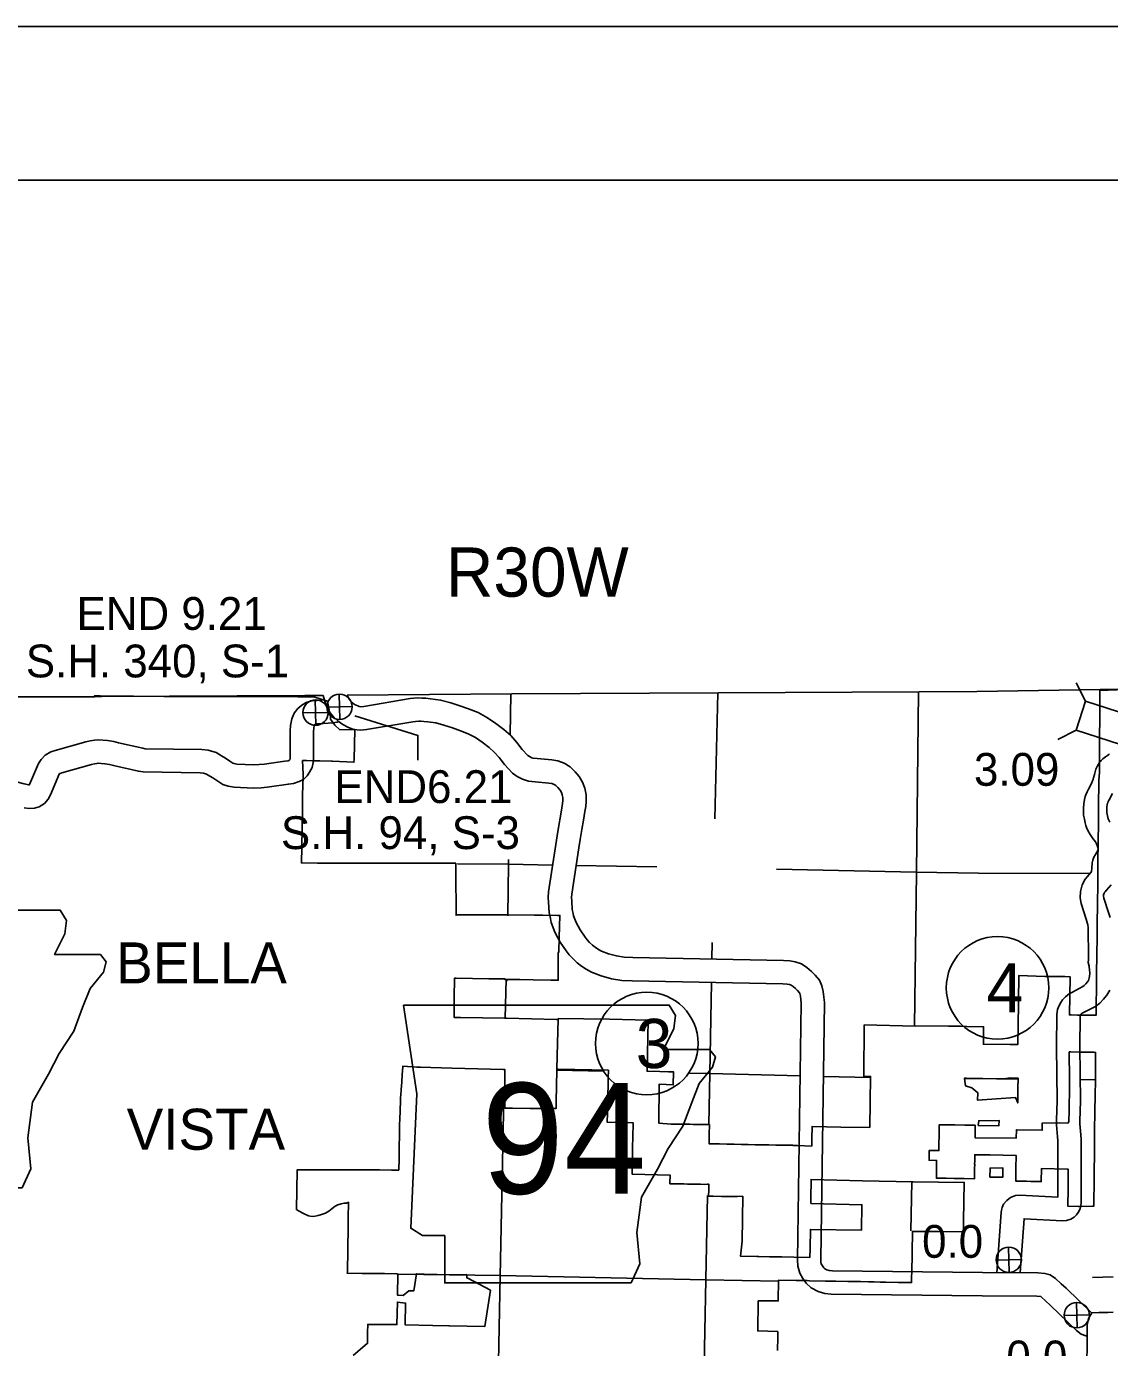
# Model space of a CAD drawing. Extents: x 77230 to 630905, y 790554 to 1662844.
# Drawn here: x 232709 to 260599, y 1621421 to 1655440 of the extents above; entities that cross this region are included whole.
import ezdxf

# ---------------------------------------------------------------- set-up
doc = ezdxf.new("R2010")
doc.units = 0
for name, color, linetype in [('Level 12', 7, 'Continuous'), ('Level 14', 7, 'Continuous'), ('Level 16', 7, 'Continuous'), ('Level 19', 7, 'Continuous'), ('Level 22', 7, 'Continuous'), ('Level 24', 7, 'Continuous'), ('Level 27', 7, 'Continuous'), ('Level 28', 7, 'Continuous'), ('Level 31', 7, 'Continuous'), ('Level 32', 7, 'Continuous'), ('Level 33', 7, 'Continuous'), ('Level 34', 7, 'Continuous')]:
    doc.layers.add(name, color=color, linetype=linetype)

msp = doc.modelspace()

# ---------------------------------------------------------------- linework, layer by layer
at = {"layer": 'Level 12'}
for points in [[(232156, 1638165), (233990, 1638176), (234030, 1638177), (234467, 1638179), (234460, 1638204), (234607, 1638202), (235470, 1638195), (236248, 1638188), (237126, 1638186), (238276, 1638185), (238909, 1638184), (238943, 1638183), (238967, 1638183), (238981, 1638183), (239696, 1638175), (239859, 1638174), (240133, 1638172), (240460, 1638068), (240502, 1637834), (240487, 1637833), (240529, 1637759), (240535, 1637603), (240653, 1637446), (240780, 1637327), (241114, 1637334), (241164, 1637335), (241144, 1636564), (241142, 1636494), (240590, 1636519), (240566, 1636520), (240265, 1636527), (240104, 1636531), (239917, 1636536), (239856, 1636538), (239822, 1636536), (239834, 1636177), (239832, 1636087), (239832, 1636074), (239831, 1636022), (239831, 1636014), (239830, 1636003)], [(260281, 1632286), (260288, 1632882), (260294, 1633326), (260296, 1633542), (260297, 1633575), (260297, 1633612), (260298, 1633714), (260301, 1633909), (260307, 1634453), (260313, 1634927), (260318, 1635179), (260317, 1635184), (260316, 1635188), (260317, 1635269), (260317, 1635294), (260318, 1635312), (260326, 1636044), (260330, 1636118), (260337, 1636245), (260340, 1636766), (260341, 1636820), (260341, 1636834), (260343, 1637228), (260347, 1637543), (260347, 1637562), (260347, 1637581), (260352, 1638340), (260999, 1638368)], [(239830, 1636003), (239821, 1635537), (239820, 1635503), (239821, 1635497), (239821, 1635490), (239820, 1635481), (239819, 1635475), (239816, 1635279), (239798, 1634326), (239797, 1634269), (239791, 1633937), (239790, 1633899), (239801, 1633899), (240203, 1633898), (240628, 1633897), (240964, 1633896), (241291, 1633896), (241914, 1633895), (241922, 1633895), (242202, 1633895), (242466, 1633895), (243765, 1633893), (243765, 1633874), (243766, 1633784), (243766, 1633607), (243773, 1632632), (243773, 1632554), (243785, 1632563), (245097, 1632564), (245113, 1632563), (245794, 1632556), (245939, 1632555), (246004, 1632554), (246385, 1632550), (246410, 1632549), (246444, 1632549), (246426, 1631983), (246415, 1631622), (246403, 1631574), (246403, 1631498), (246402, 1631213), (246402, 1631204), (246402, 1630878), (246215, 1630884), (245759, 1630894), (245416, 1630895), (245398, 1630896), (245372, 1630895), (245338, 1630895), (245034, 1630896), (245034, 1630915), (244850, 1630916), (244737, 1630916), (244615, 1630917), (243774, 1630936), (243762, 1630936), (243744, 1630937), (243732, 1630937), (243729, 1630898), (243731, 1630891), (243731, 1630882), (243727, 1630474), (243725, 1630277), (243722, 1629985), (243722, 1629974), (243721, 1629924), (243823, 1629922), (243889, 1629921), (245020, 1629905), (245029, 1629905), (245030, 1629905), (245061, 1629904), (245070, 1629904), (246362, 1629868), (246403, 1629867), (246387, 1629261), (246369, 1628593), (246368, 1628561), (246350, 1627755), (246349, 1627711), (246346, 1627576), (246333, 1627575), (246306, 1627574), (245676, 1627576), (245223, 1627584), (245024, 1627588), (245024, 1627819), (245025, 1628585), (244982, 1628585), (244982, 1628579), (244330, 1628600), (243661, 1628617), (242856, 1628639), (242766, 1628641), (242401, 1628663), (242399, 1628644), (242394, 1628562), (242385, 1628435), (242384, 1628426), (242374, 1628279)], [(249641, 1625634), (249540, 1625636), (249279, 1625640), (249279, 1625667), (249283, 1625861), (248957, 1625870), (248307, 1625882), (248319, 1626546), (248325, 1626874), (248330, 1627164), (248331, 1627212), (247667, 1627225), (247676, 1627680), (247678, 1627752), (247682, 1627954), (247686, 1628156), (247690, 1628358), (247694, 1628561), (246405, 1628589), (246369, 1628593), (246387, 1629261), (246403, 1629867), (246404, 1629894), (247722, 1629876), (248384, 1629864), (248715, 1629854), (248689, 1628535), (249020, 1628527), (249239, 1628521), (249372, 1628518), (249364, 1628186), (249003, 1628204), (248995, 1627197), (249310, 1627177), (249606, 1627173), (249698, 1627171), (249789, 1627170), (249880, 1627168), (249971, 1627166), (250072, 1627164), (250297, 1627163), (250290, 1626905), (250289, 1626807), (250289, 1626719), (250289, 1626672), (250293, 1626671), (250377, 1626669), (250467, 1626666), (250557, 1626663), (250747, 1626659), (250935, 1626655), (251115, 1626652), (251294, 1626648), (251474, 1626644), (251646, 1626640), (251825, 1626638), (252005, 1626635), (252113, 1626634), (252225, 1626632), (252261, 1626632), (252337, 1626630), (252434, 1626629), (252450, 1626628), (252564, 1626626), (252932, 1626611), (252934, 1626724), (252936, 1626840), (252940, 1627070), (252941, 1627114), (253683, 1627093), (254425, 1627091), (254445, 1628402), (254271, 1628406), (254281, 1629729), (255592, 1629697), (255592, 1629709), (256451, 1629697), (256757, 1629693), (256921, 1629690), (257342, 1629683), (257356, 1629683), (257350, 1629233), (258035, 1629224), (258233, 1629222), (258243, 1629668), (258262, 1630999), (258936, 1630978), (259238, 1630974), (259447, 1630972), (259582, 1630970), (259564, 1629986), (259609, 1629986), (259772, 1629984), (259995, 1629981), (260170, 1629979), (260253, 1629978), (260265, 1630961), (260273, 1631624), (260277, 1631901), (260281, 1632286)], [(242374, 1628279), (242373, 1628265), (242366, 1628154), (242365, 1628144), (242361, 1628084), (242360, 1628069), (242359, 1628059), (242358, 1628042), (242356, 1628008), (242354, 1627974), (242351, 1627936), (242345, 1627852), (242345, 1627843), (242343, 1627781), (242342, 1627762), (242321, 1627296), (242318, 1627174), (242316, 1627032), (242305, 1626448), (242305, 1626403), (242303, 1626338), (242303, 1626323), (242303, 1626290), (242297, 1625991), (242205, 1625992), (242112, 1625993), (241803, 1625994), (241701, 1625994), (241627, 1625995), (241589, 1625995), (241568, 1625995), (241056, 1625999), (241006, 1625999), (239680, 1625997), (239680, 1625993), (239659, 1624973), (239716, 1624946), (239863, 1624867), (239975, 1624809), (240070, 1624797), (240142, 1624807), (240222, 1624821), (240308, 1624846), (240406, 1624883), (240495, 1624935), (240581, 1625003), (240655, 1625062), (240730, 1625098), (240813, 1625124), (240888, 1625141), (240953, 1625143), (241000, 1625161), (240997, 1624755), (240997, 1624736), (240997, 1624674), (240995, 1624533), (240976, 1623375), (240971, 1623336), (241350, 1623332), (241926, 1623326), (242249, 1623321), (242275, 1623315), (242264, 1622770), (242281, 1622769), (242286, 1622769), (242414, 1622762), (242560, 1622878), (242684, 1622881), (242749, 1623320), (242947, 1623314), (243616, 1623294), (244046, 1623299), (244045, 1623221), (244075, 1623206), (244661, 1622898), (244517, 1621965), (243600, 1621978), (243585, 1621979), (243174, 1621991), (243167, 1621990), (242471, 1622007), (242461, 1622007), (242473, 1622566), (242261, 1622593), (242249, 1622011), (242228, 1622012), (242201, 1622012), (242132, 1622013), (242117, 1622013), (241969, 1622016), (241818, 1622015), (241668, 1622017), (241498, 1622018), (241496, 1621970), (241496, 1621958), (241491, 1621868), (241492, 1621718), (241493, 1621531), (241124, 1621221)], [(252050, 1621349), (252052, 1621449), (252054, 1621588), (252055, 1621697), (252056, 1621755), (252057, 1621833), (251539, 1621850), (251551, 1622622), (252069, 1622624), (252076, 1623153), (252076, 1623158), (252527, 1623148), (252816, 1623144), (252872, 1623143), (253282, 1623135), (253526, 1623131), (253548, 1623130), (253856, 1623125), (253977, 1623122), (254186, 1623119), (254388, 1623115), (254535, 1623112), (254689, 1623109), (254840, 1623106), (255160, 1623100), (255369, 1623096), (255500, 1623094), (255503, 1623279), (255504, 1623329), (255524, 1624414), (256184, 1624406), (256836, 1624398), (256840, 1624684), (256857, 1625674), (256197, 1625681), (255534, 1625688), (255534, 1625689), (254234, 1625716), (252915, 1625751), (252913, 1625528), (252911, 1625479), (252906, 1625290), (252908, 1625133), (254222, 1625100), (254210, 1624440), (252897, 1624465), (252888, 1623972), (252883, 1623742), (252472, 1623750), (252157, 1623756), (251843, 1623761), (251570, 1623768), (251517, 1623768), (251093, 1623777), (251137, 1624161), (251156, 1625318), (251022, 1625308), (250877, 1625311), (250842, 1625312), (250711, 1625315), (250606, 1625315), (250393, 1625318), (250275, 1625319), (250278, 1625481), (250281, 1625626), (250250, 1625627), (250167, 1625624), (250067, 1625625), (250016, 1625626), (249915, 1625628), (249824, 1625630), (249733, 1625632), (249641, 1625634)]]:
    msp.add_lwpolyline(points, dxfattribs=at)
for points in [[(259561, 1629037), (259570, 1628320), (259564, 1627926), (259562, 1627743), (259559, 1627560), (259559, 1627523), (259554, 1627231), (259528, 1627203), (259298, 1627205), (258865, 1627203), (258865, 1627019), (258199, 1627029), (258196, 1626814), (257138, 1626824), (257137, 1627038), (257138, 1627144), (257097, 1627147), (257010, 1627147), (256873, 1627148), (256617, 1627153), (256214, 1627159), (256213, 1627154), (256213, 1627131), (256212, 1627050), (256204, 1626498), (256203, 1626493), (255958, 1626498), (255953, 1626245), (256147, 1626241), (256139, 1625780), (256199, 1625784), (256395, 1625781), (256598, 1625773), (256851, 1625771), (257122, 1625767), (257124, 1625967), (257124, 1625969), (257125, 1626049), (257126, 1626127), (257125, 1626155), (257127, 1626208), (257128, 1626288), (257128, 1626388), (257328, 1626385), (257527, 1626382), (257859, 1626376), (258187, 1626370), (258191, 1626371), (258188, 1626039), (258187, 1626035), (258185, 1625801), (258183, 1625707), (258194, 1625706), (258207, 1625706), (258366, 1625704), (258463, 1625703), (258570, 1625701), (258670, 1625700), (258842, 1625697), (258848, 1626033), (259511, 1626015), (259537, 1626014), (259536, 1625930), (259533, 1625685), (259531, 1625509), (259530, 1625455), (259529, 1625354), (259527, 1625228), (259525, 1625059), (259801, 1625056), (259828, 1625056), (260158, 1625058), (260194, 1625058), (260197, 1625300), (260200, 1625556), (260201, 1625677), (260204, 1625922), (260211, 1626446), (260215, 1626991), (260221, 1627510), (260228, 1627916), (260233, 1628308), (260240, 1629023), (260190, 1629024), (260016, 1629027), (259860, 1629030), (259601, 1629036)], [(258241, 1628095), (258243, 1628361), (258057, 1628365), (257862, 1628343), (257688, 1628345), (257340, 1628350), (256919, 1628355), (256863, 1628356), (256873, 1628284), (256890, 1628158), (257051, 1628109), (257205, 1627983), (257205, 1627977), (257201, 1627790), (258178, 1627859), (258235, 1627719)], [(257220, 1627143), (257750, 1627134), (257760, 1627266), (257230, 1627261)], [(257523, 1626043), (257522, 1626043), (257522, 1626040), (257521, 1625963), (257520, 1625865), (257520, 1625809), (257850, 1625805), (257854, 1626047)]]:
    msp.add_lwpolyline(points, close=True, dxfattribs=at)
at = {"layer": 'Level 14'}
for points in [[(220456, 1638182), (224686, 1638186), (229993, 1638178), (234648, 1638189), (239874, 1638210), (240352, 1638214)], [(240968, 1638218), (245204, 1638251), (250522, 1638281), (255697, 1638310), (257182, 1638315)], [(257182, 1638315), (260885, 1638375)]]:
    msp.add_lwpolyline(points, dxfattribs=at)
at = {"layer": 'Level 16'}
for points in [[(245184, 1638244), (245169, 1637196)], [(250512, 1638279), (250433, 1635037)], [(255681, 1638306), (255627, 1633657), (255573, 1629697)], [(245121, 1633989), (245119, 1633866), (245102, 1632538)], [(243806, 1633877), (245123, 1633868), (246259, 1633847)], [(246866, 1633836), (248944, 1633798)], [(252027, 1633737), (255623, 1633661), (257222, 1633636)], [(257222, 1633636), (260098, 1633625)], [(250368, 1631855), (250360, 1631429)], [(245059, 1630907), (245039, 1629905)], [(245081, 1630896), (245081, 1630857)], [(250349, 1630821), (250307, 1628474), (250281, 1627165)], [(246368, 1628566), (247574, 1628538)], [(249782, 1628488), (250307, 1628476), (252632, 1628420)], [(253229, 1628405), (254445, 1628375)], [(256864, 1628347), (257278, 1628346)], [(258243, 1628336), (257278, 1628346)], [(260207, 1628317), (259839, 1628320)], [(244999, 1627881), (244910, 1623261), (244808, 1617974)], [(255508, 1625689), (255486, 1624424)], [(250245, 1625334), (250202, 1623165), (250100, 1617874)], [(242285, 1623309), (244914, 1623273), (250202, 1623167), (252076, 1623135)]]:
    msp.add_lwpolyline(points, dxfattribs=at)
at = {"layer": 'Level 19'}
for p, q in [((259979, 1638070), (259739, 1638541)), ((259735, 1637317), (259265, 1637077)), ((260691, 1623240), (260163, 1623223))]:
    msp.add_line(p, q, dxfattribs=at)
msp.add_lwpolyline([(262240, 1637339), (259979, 1638070), (259735, 1637317), (261996, 1636586)], close=True, dxfattribs=at)
at = {"layer": 'Level 22'}
for points in [[(234562, 1637067), (234800, 1637052), (234960, 1637024), (235083, 1636997), (235709, 1636852), (235769, 1636842), (237227, 1636824), (237392, 1636802), (237593, 1636741), (237732, 1636656), (237836, 1636599), (237945, 1636520), (238022, 1636472), (238056, 1636460), (238130, 1636447), (238558, 1636426), (238706, 1636433), (238836, 1636447), (239007, 1636471), (239242, 1636501), (239367, 1636525), (239448, 1636533), (239481, 1636546), (239484, 1636551), (239496, 1636572), (239499, 1636623), (239502, 1637302), (239508, 1637441), (239541, 1637615), (239605, 1637760), (239699, 1637879), (239801, 1637961), (239915, 1638034), (240080, 1638081), (240193, 1638085), (240380, 1638097)], [(240352, 1638214), (240406, 1638006), (240463, 1637878), (240528, 1637764), (240614, 1637659), (240732, 1637549), (240854, 1637466), (240989, 1637398), (241129, 1637339), (241311, 1637321), (241468, 1637334), (242662, 1637536), (242730, 1637542), (242809, 1637548), (242869, 1637547), (242945, 1637543), (243046, 1637533), (243252, 1637504), (243459, 1637448), (243678, 1637375), (243890, 1637304), (244083, 1637228), (244270, 1637127), (244442, 1637008), (244624, 1636869), (244755, 1636754), (244879, 1636614), (245021, 1636436), (245223, 1636215), (245346, 1636130), (245481, 1636056), (245637, 1636006), (245808, 1635990), (246162, 1635956), (246240, 1635943), (246295, 1635922), (246342, 1635896), (246391, 1635845), (246449, 1635776), (246483, 1635718), (246508, 1635651), (246523, 1635585), (246523, 1635512), (246514, 1635428), (246498, 1635321), (246459, 1635101), (246418, 1634863), (246371, 1634599), (246341, 1634377), (246151, 1633158), (246145, 1633009), (246151, 1632888), (246168, 1632625), (246200, 1632468), (246223, 1632369), (246317, 1632121), (246451, 1631864), (246606, 1631641), (246688, 1631530), (246787, 1631428), (246892, 1631328), (247006, 1631241), (247125, 1631161), (247259, 1631087), (247509, 1630989), (247773, 1630917), (248040, 1630874), (248306, 1630862), (252184, 1630786), (252295, 1630781), (252354, 1630769), (252401, 1630754), (252450, 1630721), (252513, 1630670), (252566, 1630612), (252612, 1630557), (252620, 1630540), (252637, 1630473), (252649, 1630387), (252655, 1630289), (252562, 1623684), (252570, 1623520), (252621, 1623341), (252701, 1623203), (252784, 1623082), (252913, 1622959), (253093, 1622864), (253267, 1622816), (253430, 1622799), (257321, 1622751)], [(240968, 1638218), (240999, 1638150), (241025, 1638105), (241052, 1638071), (241108, 1638019), (241159, 1637984), (241241, 1637943), (241277, 1637928), (241316, 1637924), (241394, 1637930), (242586, 1638132), (242682, 1638140), (242790, 1638148), (242890, 1638147), (242990, 1638141), (243117, 1638129), (243374, 1638093), (243633, 1638022), (243867, 1637944), (244095, 1637868), (244337, 1637773), (244584, 1637639), (244795, 1637494), (245004, 1637334), (245179, 1637180), (245339, 1637000), (245477, 1636825), (245620, 1636670), (245661, 1636641), (245719, 1636609), (245756, 1636597), (245864, 1636588), (246238, 1636551), (246396, 1636526), (246554, 1636466), (246712, 1636375), (246837, 1636248), (246942, 1636122), (247026, 1635977), (247084, 1635825), (247123, 1635652), (247123, 1635481), (247110, 1635352), (247090, 1635223), (247050, 1634998), (247009, 1634759), (246964, 1634506), (246935, 1634291), (246749, 1633100), (246746, 1633013), (246750, 1632922), (246764, 1632705), (246787, 1632594), (246799, 1632542), (246865, 1632367), (246965, 1632175), (247094, 1631990), (247147, 1631918), (247209, 1631854), (247282, 1631784), (247354, 1631729), (247436, 1631675), (247515, 1631631), (247699, 1631559), (247899, 1631504), (248101, 1631472), (248326, 1631462), (252204, 1631385), (252365, 1631378), (252505, 1631351), (252667, 1631298), (252808, 1631204), (252927, 1631106), (253015, 1631009), (253127, 1630878), (253189, 1630736), (253227, 1630587), (253246, 1630446), (253255, 1630304), (253162, 1623693), (253166, 1623617), (253177, 1623577), (253208, 1623524), (253242, 1623474), (253267, 1623451), (253316, 1623425), (253378, 1623408), (253464, 1623399), (257328, 1623351)], [(234539, 1636468), (234728, 1636455), (234845, 1636434), (234953, 1636411), (235593, 1636263), (235717, 1636243), (237183, 1636224), (237265, 1636213), (237346, 1636189), (237431, 1636137), (237513, 1636092), (237609, 1636022), (237766, 1635924), (237908, 1635877), (238062, 1635850), (238557, 1635825), (238752, 1635834), (238910, 1635852), (239086, 1635876), (239337, 1635908), (239455, 1635931), (239589, 1635945), (239731, 1635999), (239841, 1636049), (239935, 1636145), (239996, 1636236), (240064, 1636358), (240092, 1636486), (240099, 1636605), (240102, 1637288), (240106, 1637373), (240117, 1637435), (240123, 1637448), (240128, 1637454), (240152, 1637473), (240165, 1637481), (240175, 1637484), (240222, 1637486), (240477, 1637501), (240592, 1637512), (240707, 1637529), (240727, 1637537)], [(230293, 1635300), (230413, 1635326), (230510, 1635353), (230607, 1635391), (231803, 1635939), (231935, 1635988), (232045, 1636007), (232216, 1636025), (232352, 1636005), (232422, 1635996), (232647, 1635938), (232770, 1635909), (232782, 1635907), (232788, 1635918), (233020, 1636461), (233087, 1636568), (233190, 1636678), (233334, 1636758), (233450, 1636796), (234237, 1637021), (234354, 1637046), (234458, 1637063), (234562, 1637067)], [(260355, 1636501), (260385, 1636537), (260430, 1636583), (260491, 1636634), (260542, 1636669), (260580, 1636695), (260601, 1636711)], [(232648, 1635321), (232780, 1635298), (232915, 1635308), (233039, 1635346), (233175, 1635432), (233265, 1635542), (233327, 1635652), (233553, 1636183), (233564, 1636200), (233574, 1636205), (233625, 1636222), (234382, 1636439), (234464, 1636456), (234519, 1636465), (234571, 1636467)], [(257694, 1623347), (257806, 1624899), (257813, 1624960), (257832, 1625029), (257869, 1625114), (257950, 1625208), (258051, 1625288), (258181, 1625334), (258290, 1625343), (259267, 1625293), (259271, 1626665), (259268, 1626753), (259261, 1626844), (259230, 1627156), (259231, 1627273), (259248, 1627771), (259236, 1629169), (259238, 1629994), (259262, 1630125), (259294, 1630213), (259343, 1630307), (259390, 1630373), (259462, 1630455), (259566, 1630534), (259626, 1630568), (259913, 1630715), (259948, 1630742), (259992, 1630788), (260031, 1630836), (260054, 1630876), (260076, 1630940), (260082, 1630979), (260088, 1631060), (260089, 1631083), (260084, 1631132), (260070, 1631238), (260047, 1631335), (260056, 1631415), (260057, 1631477), (260048, 1632231), (260040, 1632313), (260034, 1632336), (260000, 1632452), (259870, 1632854), (259846, 1633000), (259848, 1633167), (259893, 1633334), (259970, 1633481), (260031, 1633552), (260068, 1633594), (260128, 1633664), (260136, 1633686), (260139, 1633758), (260155, 1633904), (260170, 1633970), (260193, 1634046), (260233, 1634121), (260293, 1634223), (260301, 1634248), (260305, 1634259), (260302, 1634275), (260284, 1634346), (260261, 1634395), (260233, 1634442), (260171, 1634529), (260102, 1634630), (260042, 1634733), (260008, 1634810), (259987, 1634868), (259971, 1634936), (259950, 1635028), (259930, 1635128), (259925, 1635245), (259925, 1635313), (259935, 1635424), (259954, 1635532), (259975, 1635607), (259991, 1635657), (260022, 1635730), (260058, 1635802), (260134, 1635946), (260164, 1636018), (260177, 1636057), (260189, 1636092), (260208, 1636175), (260242, 1636314), (260281, 1636382), (260316, 1636445), (260343, 1636484)], [(260610, 1634950), (260578, 1635005), (260566, 1635032), (260562, 1635043), (260555, 1635073), (260537, 1635153), (260528, 1635198), (260525, 1635256), (260525, 1635287), (260530, 1635345), (260540, 1635399), (260550, 1635436), (260555, 1635450), (260567, 1635478), (260592, 1635527), (260677, 1635690)], [(260612, 1632497), (260573, 1632628), (260455, 1632996), (260447, 1633045), (260447, 1633084), (260456, 1633115), (260471, 1633144), (260483, 1633158), (260519, 1633199), (260637, 1633336)], [(258296, 1623351), (258396, 1624737), (259389, 1624686), (259493, 1624692), (259604, 1624730), (259686, 1624782), (259745, 1624837), (259794, 1624901), (259839, 1624990), (259861, 1625087), (259867, 1625137), (259871, 1626674), (259868, 1626785), (259859, 1626896), (259830, 1627185), (259831, 1627262), (259848, 1627764), (259836, 1629171), (259838, 1629937), (259843, 1629967), (259845, 1629972), (259856, 1629994), (259862, 1630002), (259873, 1630015), (259897, 1630032), (259911, 1630041), (260233, 1630205), (260348, 1630292), (260442, 1630391), (260529, 1630498), (260603, 1630628)], [(257326, 1623351), (258750, 1623343), (258933, 1623330), (259070, 1623293), (259210, 1623203), (259356, 1623062), (259485, 1622947), (260133, 1622318), (260135, 1622316), (260137, 1622316), (260322, 1622320)], [(257323, 1622751), (258727, 1622743), (258826, 1622736), (258835, 1622730), (258948, 1622622), (259077, 1622507), (259745, 1621858), (259868, 1621768), (259992, 1621724), (260027, 1621722)], [(260025, 1622023), (260063, 1622184), (260142, 1622318)], [(260322, 1622320), (260553, 1622326), (260691, 1622334)], [(260025, 1622023), (260012, 1620513), (260010, 1620423), (259710, 1618064)]]:
    msp.add_lwpolyline(points, dxfattribs=at)
at = {"layer": 'Level 24'}
for points in [[(226734, 1632687), (227077, 1630403), (226925, 1626939), (227229, 1626749), (227800, 1626749), (227800, 1625531), (232596, 1625531), (232825, 1626025), (232749, 1626825), (232863, 1627738), (233281, 1628462), (233548, 1628994), (233929, 1629565), (234157, 1630175), (234347, 1630669), (234690, 1631088), (234766, 1631355), (234614, 1631545), (233434, 1631545), (233700, 1632078), (233738, 1632420), (233580, 1632683)], [(242416, 1630242), (242758, 1627958), (242606, 1624494), (242911, 1624304), (243482, 1624304), (243482, 1623086), (248278, 1623086), (248506, 1623581), (248430, 1624380), (248544, 1625294), (248963, 1626017), (249230, 1626550), (249610, 1627121), (249839, 1627730), (250029, 1628225), (250372, 1628643), (250448, 1628910), (250295, 1629100), (249115, 1629100), (249382, 1629633), (249420, 1629976), (249262, 1630239)]]:
    msp.add_lwpolyline(points, close=True, dxfattribs=at)
at = {"layer": 'Level 28'}
for p, q in [((77230, 1655440), (372910, 1655440)), ((367630, 1651480), (93070, 1651480))]:
    msp.add_line(p, q, dxfattribs=at)
at = {"layer": 'Level 31'}
msp.add_lwpolyline([(241167, 1637688), (242789, 1637182), (242789, 1636543)], dxfattribs=at)
at = {"layer": 'Level 33'}
for centre in [(257715, 1630684), (248683, 1629251)]:
    msp.add_circle(centre, 1320, dxfattribs=at)
at = {"layer": 'Level 34'}
for p, q in [((240162, 1637445), (240147, 1638096)), ((240778, 1637594), (240763, 1638245)), ((239829, 1637763), (240480, 1637778)), ((240445, 1637912), (241096, 1637927)), ((258013, 1623356), (257998, 1624007)), ((257680, 1623674), (258331, 1623689)), ((259762, 1621928), (259747, 1622579)), ((259429, 1622246), (260080, 1622261))]:
    msp.add_line(p, q, dxfattribs=at)
for centre in [(240154, 1637771), (240771, 1637920), (258005, 1623682), (259754, 1622254)]:
    msp.add_circle(centre, 326, dxfattribs=at)

# ---------------------------------------------------------------- texts
at = {"layer": 'Level 24'}
msp.add_text('94', height=2851.2, dxfattribs=at).set_placement((244428, 1625382))
at = {"layer": 'Level 27'}
for s, p in [('BELLA', (235020, 1630798)), ('VISTA', (235290, 1626515))]:
    msp.add_text(s, height=1056, dxfattribs=at).set_placement(p)
at = {"layer": 'Level 28'}
msp.add_text('R30W', height=1267.2, dxfattribs=at).set_placement((243509, 1640756))
at = {"layer": 'Level 31'}
for s, p in [('END 9.21', (233999, 1639901)), ('S.H. 340, S-1', (232693, 1638678)), ('END6.21', (240640, 1635442)), ('S.H. 94, S-3', (239263, 1634257)), ('0.0', (255772, 1623733)), ('0.0', (257942, 1620756))]:
    msp.add_text(s, height=844.8, dxfattribs=at).set_placement(p)
at = {"layer": 'Level 32'}
msp.add_text('3.09', height=844.8, dxfattribs=at).set_placement((257108, 1635887))
at = {"layer": 'Level 33'}
for s, p in [('4', (257432, 1630050)), ('3', (248400, 1628618))]:
    msp.add_text(s, height=1267, dxfattribs=at).set_placement(p)

doc.saveas('drawing.dxf')
